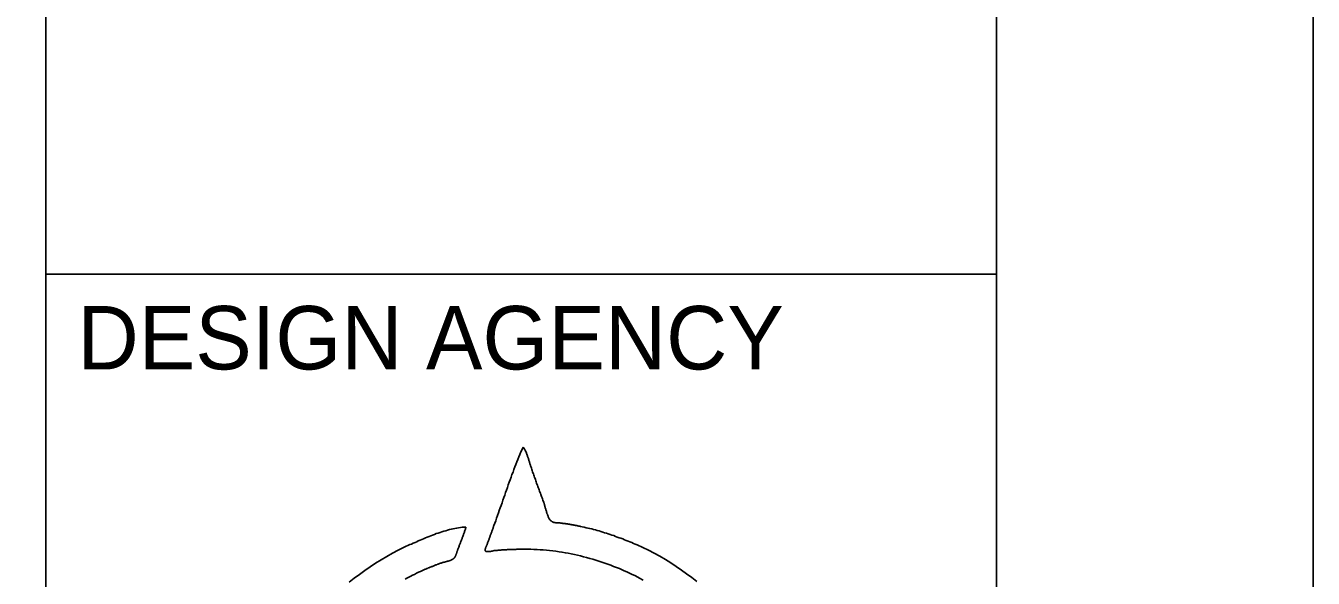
# Model space of a CAD drawing. Extents: x 0 to 170, y 0 to 110.
# Drawn here: x 159.84 to 170, y 20.1 to 24.46 of the extents above; entities that cross this region are included whole.
import ezdxf

# ---------------------------------------------------------------- set-up
doc = ezdxf.new("R2010")
doc.units = 0
for name, color, linetype in [('SH_Border', 7, 'Continuous'), ('SH_Cut_Line', 7, 'Continuous'), ('SH_Data', 7, 'Continuous'), ('SH_Text', 7, 'Continuous')]:
    doc.layers.add(name, color=color, linetype=linetype)

msp = doc.modelspace()

# ---------------------------------------------------------------- linework, layer by layer
at = {"layer": 'SH_Border'}
for p, q in [((160, 2.5), (160, 107.5)), ((160, 22.5), (167.5, 22.5))]:
    msp.add_line(p, q, dxfattribs=at)
msp.add_lwpolyline([(7.5, 107.5), (167.5, 107.5), (167.5, 2.5), (7.5, 2.5)], close=True, dxfattribs=at)
at = {"layer": 'SH_Cut_Line'}
msp.add_lwpolyline([(0, 0), (170, 0), (170, 110), (0, 110)], close=True, dxfattribs=at)
at = {"layer": 'SH_Text'}
for points in [[(163.766, 21.138), (163.758, 21.119), (163.749, 21.1), (163.741, 21.08), (163.733, 21.06), (163.725, 21.04), (163.717, 21.021), (163.709, 21.001), (163.701, 20.981), (163.693, 20.961), (163.686, 20.941), (163.678, 20.921), (163.671, 20.901), (163.664, 20.88), (163.656, 20.86), (163.649, 20.84), (163.642, 20.819), (163.635, 20.799), (163.628, 20.779), (163.621, 20.759), (163.613, 20.739), (163.607, 20.718), (163.6, 20.698), (163.592, 20.678), (163.586, 20.658), (163.578, 20.638), (163.571, 20.618), (163.564, 20.597), (163.557, 20.577), (163.55, 20.557), (163.543, 20.537), (163.535, 20.518)], [(163.828, 20.98), (163.826, 20.984), (163.824, 20.989), (163.823, 20.994), (163.821, 20.999), (163.82, 21.004), (163.818, 21.01), (163.817, 21.015), (163.815, 21.021), (163.813, 21.026), (163.812, 21.032), (163.81, 21.037), (163.809, 21.043), (163.807, 21.048), (163.805, 21.053), (163.803, 21.059), (163.801, 21.064), (163.8, 21.07), (163.798, 21.075), (163.796, 21.081), (163.793, 21.086), (163.792, 21.091), (163.789, 21.097), (163.787, 21.101), (163.785, 21.107), (163.783, 21.112), (163.78, 21.117), (163.778, 21.121), (163.775, 21.126), (163.772, 21.13), (163.769, 21.134), (163.766, 21.138)], [(163.928, 20.702), (163.925, 20.711), (163.922, 20.72), (163.918, 20.729), (163.915, 20.738), (163.912, 20.747), (163.909, 20.756), (163.905, 20.764), (163.902, 20.773), (163.898, 20.782), (163.895, 20.791), (163.892, 20.8), (163.889, 20.809), (163.885, 20.818), (163.882, 20.827), (163.879, 20.836), (163.875, 20.845), (163.872, 20.854), (163.869, 20.863), (163.866, 20.872), (163.863, 20.881), (163.86, 20.89), (163.856, 20.898), (163.853, 20.907), (163.85, 20.916), (163.847, 20.926), (163.843, 20.935), (163.84, 20.943), (163.837, 20.952), (163.834, 20.961), (163.831, 20.97), (163.828, 20.98)], [(163.989, 20.553), (163.986, 20.556), (163.983, 20.559), (163.98, 20.562), (163.977, 20.565), (163.975, 20.569), (163.972, 20.573), (163.969, 20.578), (163.967, 20.582), (163.964, 20.587), (163.963, 20.593), (163.96, 20.598), (163.958, 20.603), (163.957, 20.609), (163.954, 20.614), (163.952, 20.619), (163.95, 20.625), (163.949, 20.631), (163.947, 20.637), (163.946, 20.642), (163.944, 20.648), (163.943, 20.654), (163.941, 20.659), (163.94, 20.665), (163.938, 20.67), (163.937, 20.675), (163.935, 20.68), (163.934, 20.685), (163.932, 20.69), (163.931, 20.694), (163.93, 20.698), (163.928, 20.702)], [(164.069, 20.538), (164.067, 20.538), (164.064, 20.538), (164.062, 20.538), (164.06, 20.538), (164.057, 20.539), (164.054, 20.539), (164.052, 20.539), (164.049, 20.539), (164.046, 20.539), (164.043, 20.539), (164.04, 20.539), (164.038, 20.539), (164.035, 20.54), (164.032, 20.54), (164.029, 20.541), (164.026, 20.541), (164.023, 20.541), (164.021, 20.541), (164.018, 20.542), (164.015, 20.542), (164.012, 20.543), (164.01, 20.544), (164.007, 20.544), (164.004, 20.545), (164.002, 20.546), (164, 20.547), (163.998, 20.548), (163.995, 20.549), (163.993, 20.55), (163.991, 20.552), (163.989, 20.553)], [(164.218, 20.512), (164.213, 20.513), (164.209, 20.514), (164.204, 20.515), (164.199, 20.516), (164.194, 20.517), (164.189, 20.518), (164.184, 20.519), (164.18, 20.52), (164.175, 20.521), (164.171, 20.522), (164.166, 20.522), (164.161, 20.524), (164.156, 20.524), (164.151, 20.525), (164.146, 20.526), (164.141, 20.527), (164.137, 20.528), (164.132, 20.529), (164.127, 20.53), (164.122, 20.53), (164.117, 20.531), (164.112, 20.532), (164.107, 20.533), (164.103, 20.533), (164.098, 20.534), (164.093, 20.535), (164.089, 20.535), (164.084, 20.536), (164.079, 20.536), (164.074, 20.537), (164.069, 20.538)], [(162.873, 20.368), (162.886, 20.373), (162.899, 20.379), (162.913, 20.385), (162.926, 20.391), (162.939, 20.397), (162.953, 20.403), (162.967, 20.409), (162.981, 20.415), (162.995, 20.421), (163.009, 20.427), (163.024, 20.432), (163.038, 20.438), (163.052, 20.444), (163.067, 20.449), (163.081, 20.455), (163.096, 20.459), (163.11, 20.465), (163.125, 20.469), (163.14, 20.474), (163.155, 20.478), (163.169, 20.482), (163.184, 20.487), (163.199, 20.49), (163.213, 20.493), (163.228, 20.496), (163.242, 20.499), (163.257, 20.501), (163.272, 20.504), (163.286, 20.505), (163.301, 20.506), (163.315, 20.507)], [(163.315, 20.507), (163.313, 20.501), (163.312, 20.496), (163.31, 20.49), (163.308, 20.484), (163.306, 20.479), (163.304, 20.473), (163.302, 20.467), (163.301, 20.461), (163.298, 20.456), (163.296, 20.45), (163.295, 20.444), (163.292, 20.439), (163.29, 20.433), (163.288, 20.428), (163.286, 20.422), (163.284, 20.416), (163.282, 20.411), (163.279, 20.405), (163.278, 20.399), (163.275, 20.394), (163.273, 20.388), (163.271, 20.383), (163.269, 20.377), (163.266, 20.371), (163.264, 20.366), (163.262, 20.361), (163.26, 20.355), (163.258, 20.349), (163.256, 20.344), (163.253, 20.338), (163.252, 20.333)], [(163.535, 20.518), (163.533, 20.513), (163.532, 20.508), (163.53, 20.503), (163.529, 20.498), (163.527, 20.493), (163.525, 20.488), (163.523, 20.484), (163.521, 20.479), (163.519, 20.474), (163.518, 20.469), (163.516, 20.464), (163.515, 20.46), (163.513, 20.455), (163.511, 20.45), (163.509, 20.445), (163.507, 20.441), (163.506, 20.436), (163.504, 20.431), (163.503, 20.426), (163.501, 20.421), (163.499, 20.416), (163.497, 20.412), (163.495, 20.407), (163.493, 20.402), (163.492, 20.398), (163.49, 20.393), (163.488, 20.388), (163.486, 20.383), (163.484, 20.378), (163.483, 20.373), (163.481, 20.368)], [(164.665, 20.366), (164.651, 20.372), (164.637, 20.378), (164.623, 20.384), (164.608, 20.39), (164.594, 20.396), (164.58, 20.401), (164.566, 20.407), (164.552, 20.413), (164.538, 20.418), (164.524, 20.423), (164.509, 20.428), (164.495, 20.433), (164.481, 20.439), (164.466, 20.444), (164.452, 20.448), (164.438, 20.453), (164.423, 20.458), (164.409, 20.462), (164.394, 20.467), (164.38, 20.472), (164.365, 20.476), (164.351, 20.48), (164.336, 20.484), (164.321, 20.488), (164.307, 20.492), (164.292, 20.495), (164.277, 20.499), (164.263, 20.502), (164.248, 20.506), (164.233, 20.509), (164.218, 20.512)], [(162.394, 20.071), (162.434, 20.104), (162.475, 20.134), (162.517, 20.165), (162.559, 20.194), (162.602, 20.222), (162.646, 20.249), (162.69, 20.275), (162.735, 20.3), (162.781, 20.324), (162.827, 20.347), (162.873, 20.368)], [(163.252, 20.333), (163.25, 20.33), (163.25, 20.328), (163.249, 20.326), (163.248, 20.324), (163.247, 20.321), (163.247, 20.319), (163.246, 20.316), (163.245, 20.313), (163.244, 20.311), (163.244, 20.308), (163.242, 20.305), (163.242, 20.303), (163.241, 20.301), (163.24, 20.298), (163.239, 20.295), (163.238, 20.293), (163.237, 20.29), (163.236, 20.287), (163.235, 20.285), (163.234, 20.282), (163.233, 20.28), (163.232, 20.278), (163.23, 20.275), (163.229, 20.273), (163.228, 20.271), (163.227, 20.268), (163.225, 20.267), (163.224, 20.265), (163.222, 20.262), (163.221, 20.261), (163.219, 20.259)], [(163.481, 20.368), (163.481, 20.367), (163.48, 20.366), (163.479, 20.365), (163.479, 20.364), (163.478, 20.362), (163.478, 20.361), (163.477, 20.359), (163.476, 20.357), (163.475, 20.355), (163.475, 20.353), (163.473, 20.351), (163.473, 20.35), (163.472, 20.348), (163.471, 20.345), (163.47, 20.344), (163.47, 20.342), (163.469, 20.34), (163.469, 20.338), (163.468, 20.336), (163.467, 20.334), (163.467, 20.332), (163.467, 20.33), (163.467, 20.328), (163.466, 20.327), (163.466, 20.325), (163.466, 20.324), (163.467, 20.322), (163.467, 20.321), (163.467, 20.319), (163.468, 20.318), (163.469, 20.317)], [(163.469, 20.317), (163.47, 20.316), (163.471, 20.315), (163.473, 20.315), (163.475, 20.314), (163.477, 20.313), (163.479, 20.313), (163.481, 20.313), (163.484, 20.313), (163.487, 20.313), (163.489, 20.313), (163.492, 20.313), (163.495, 20.313), (163.498, 20.313), (163.501, 20.314), (163.504, 20.315), (163.507, 20.315), (163.51, 20.315), (163.513, 20.316), (163.516, 20.316), (163.519, 20.317), (163.523, 20.318), (163.525, 20.318), (163.528, 20.319), (163.531, 20.319), (163.533, 20.32), (163.536, 20.321), (163.538, 20.321), (163.54, 20.321), (163.543, 20.322), (163.544, 20.322), (163.546, 20.322)], [(163.546, 20.322), (163.553, 20.322), (163.561, 20.323), (163.568, 20.324), (163.575, 20.324), (163.583, 20.325), (163.59, 20.325), (163.598, 20.326), (163.605, 20.327), (163.613, 20.327), (163.62, 20.328), (163.627, 20.328), (163.635, 20.328), (163.643, 20.329), (163.65, 20.33), (163.657, 20.33), (163.664, 20.33), (163.672, 20.33), (163.68, 20.331), (163.687, 20.331), (163.694, 20.331), (163.702, 20.331), (163.709, 20.331), (163.716, 20.332), (163.724, 20.332), (163.732, 20.332), (163.739, 20.332), (163.747, 20.333), (163.754, 20.333), (163.761, 20.333), (163.769, 20.333), (163.777, 20.333)], [(163.777, 20.333), (163.801, 20.333), (163.826, 20.332), (163.851, 20.331), (163.876, 20.33), (163.901, 20.328), (163.925, 20.327), (163.95, 20.324), (163.975, 20.322), (164, 20.319), (164.024, 20.316), (164.049, 20.312), (164.073, 20.308), (164.098, 20.304), (164.122, 20.3), (164.146, 20.295), (164.171, 20.29), (164.195, 20.285), (164.219, 20.279), (164.243, 20.273), (164.267, 20.267), (164.291, 20.26), (164.315, 20.253), (164.339, 20.246), (164.363, 20.239), (164.386, 20.231), (164.41, 20.223), (164.433, 20.214), (164.457, 20.206), (164.48, 20.197), (164.503, 20.188), (164.526, 20.179)], [(165.136, 20.077), (165.097, 20.108), (165.056, 20.139), (165.016, 20.168), (164.974, 20.197), (164.931, 20.225), (164.888, 20.251), (164.845, 20.276), (164.8, 20.301), (164.756, 20.324), (164.71, 20.345), (164.665, 20.366)], [(163.13, 20.227), (163.124, 20.225), (163.118, 20.222), (163.113, 20.221), (163.107, 20.219), (163.101, 20.216), (163.096, 20.214), (163.09, 20.213), (163.084, 20.21), (163.078, 20.208), (163.073, 20.206), (163.067, 20.204), (163.061, 20.202), (163.056, 20.199), (163.05, 20.197), (163.044, 20.195), (163.039, 20.193), (163.033, 20.19), (163.027, 20.188), (163.022, 20.186), (163.016, 20.184), (163.011, 20.181), (163.005, 20.179), (162.999, 20.176), (162.994, 20.174), (162.988, 20.171), (162.983, 20.169), (162.978, 20.167), (162.972, 20.164), (162.966, 20.162), (162.961, 20.159), (162.955, 20.156)], [(163.219, 20.259), (163.217, 20.258), (163.215, 20.256), (163.212, 20.254), (163.21, 20.253), (163.207, 20.251), (163.205, 20.25), (163.202, 20.248), (163.199, 20.247), (163.196, 20.245), (163.193, 20.244), (163.19, 20.244), (163.187, 20.242), (163.184, 20.241), (163.181, 20.241), (163.178, 20.239), (163.175, 20.238), (163.172, 20.238), (163.168, 20.237), (163.165, 20.236), (163.162, 20.235), (163.159, 20.234), (163.156, 20.233), (163.153, 20.233), (163.15, 20.232), (163.147, 20.231), (163.144, 20.23), (163.141, 20.23), (163.138, 20.229), (163.135, 20.228), (163.132, 20.227), (163.13, 20.227)], [(162.955, 20.156), (162.94, 20.15), (162.925, 20.142), (162.91, 20.134), (162.894, 20.127), (162.879, 20.119), (162.864, 20.111), (162.849, 20.104), (162.834, 20.096)], [(164.526, 20.179), (164.558, 20.165), (164.589, 20.151), (164.621, 20.136), (164.652, 20.121), (164.683, 20.104), (164.714, 20.087)]]:
    msp.add_lwpolyline(points, dxfattribs=at)

# ---------------------------------------------------------------- texts
at = {"layer": 'SH_Data'}
msp.add_text('DESIGN AGENCY', height=0.5, dxfattribs=at).set_placement((160.25, 21.75))

doc.saveas('drawing.dxf')
